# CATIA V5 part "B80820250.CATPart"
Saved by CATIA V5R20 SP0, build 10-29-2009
Part number: B80820250
Revision: 4
Definition: design
Nomenclature: B80820250
Source: made
Description: NOT SPECIFIED
Bounding box of the stored display mesh (mm): x -11.818 to 11.818, y -12 to 12, z 0 to 250
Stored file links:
  C:\Users\Raffaele\Desktop\3D X SITO CF\BOLEX\4-PILLAR REF 808\B80820250.CATPart
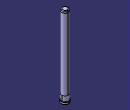
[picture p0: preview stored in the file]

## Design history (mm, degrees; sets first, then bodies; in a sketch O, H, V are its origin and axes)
Body1 "MANIFOLD_SOLID_BREP #450" (main body)
  Solid1: solid without history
